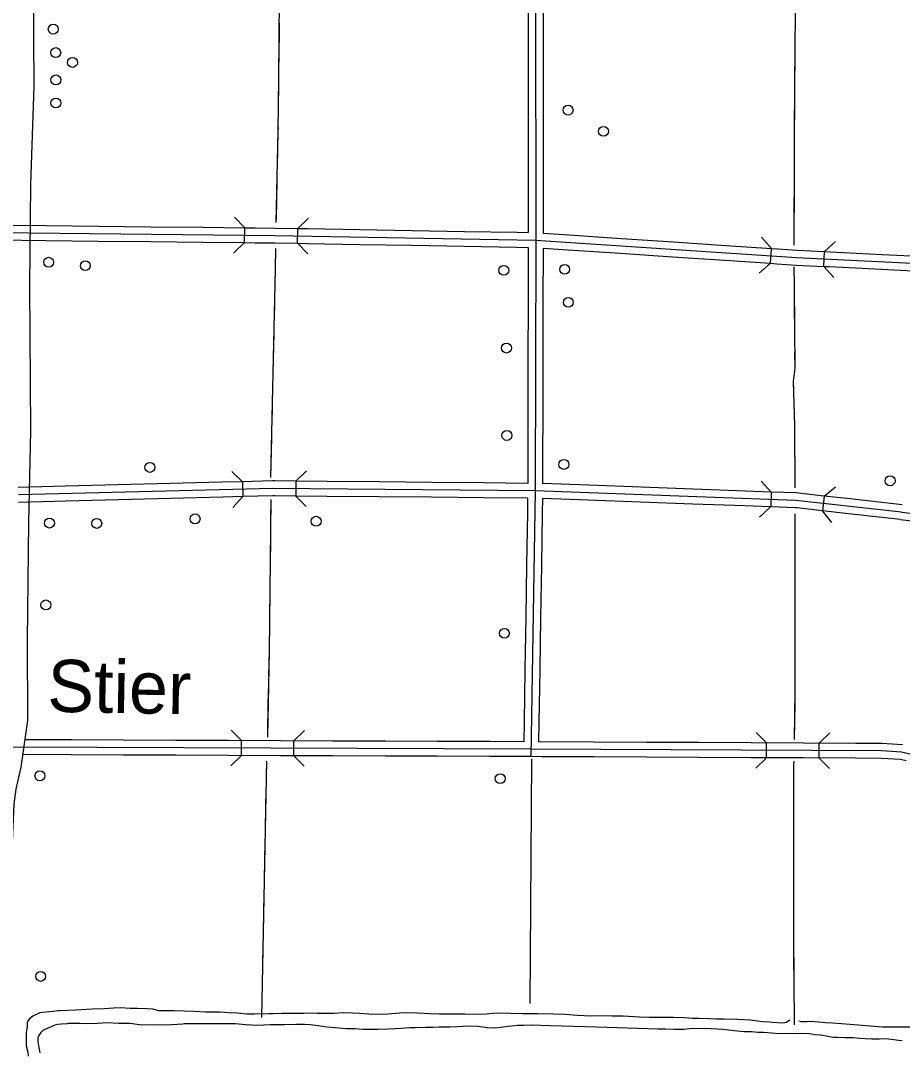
# Model space of a CAD drawing. Extents: x -4306 to 3843, y 131 to 8341.
# Drawn here: x -255 to 1170, y 190 to 1864 of the extents above; entities that cross this region are included whole.
import ezdxf

# ---------------------------------------------------------------- set-up
doc = ezdxf.new("R2010")
doc.units = 0
for name, color, linetype in [('10', 7, 'Continuous'), ('24', 7, 'Continuous'), ('32', 7, 'Continuous'), ('38', 7, 'Continuous'), ('52', 7, 'Continuous'), ('56', 7, 'Continuous'), ('57', 7, 'Continuous')]:
    doc.layers.add(name, color=color, linetype=linetype)

msp = doc.modelspace()

# ---------------------------------------------------------------- linework, layer by layer
at = {"layer": '10'}
msp.add_lwpolyline([(-229.9, 2753.2), (-230.3, 2716.3), (-231, 2305.2), (-234.2, 1917.5), (-233.4, 1758), (-238.7, 1599), (-240.3, 1434.8), (-238.9, 1200.9), (-242.2, 1053.5), (-244.1, 861.8), (-243.5, 732.4), (-254.4, 657.4), (-262.5, 621.4), (-265.5, 597.6), (-272.4, 440.2), (-274.5, 304.9), (-274.4, 293.9)], dxfattribs=at)
at = {"layer": '32'}
for p, q in [((577.4, 1912.9), (577.5, 1509.2)), ((565.4, 1901.4), (565.4, 1828.4)), ((589.4, 1900.3), (589.4, 1828.4)), ((565.4, 1828.4), (565.4, 1743.9)), ((589.4, 1828.4), (589.4, 1743.9)), ((565.4, 1743.9), (565.5, 1659.4)), ((589.4, 1743.9), (589.5, 1659.5)), ((565.5, 1659.4), (565.5, 1575)), ((589.5, 1659.5), (589.5, 1575)), ((565.5, 1575), (565.5, 1521.4)), ((589.5, 1575), (589.5, 1520.4)), ((-1096.1, 1530.1), (156, 1516.7)), ((-298, 1533.5), (-213.6, 1532.6)), ((-213.6, 1532.6), (-129.1, 1531.7)), ((-129.1, 1531.7), (-44.6, 1530.8)), ((-44.6, 1530.8), (39.9, 1529.9)), ((39.9, 1529.9), (107.4, 1529.2)), ((107.2, 1505.2), (107.4, 1529.2)), ((107.4, 1529.2), (124.4, 1529)), ((124.4, 1529), (156.1, 1528.7)), ((156.1, 1528.7), (192.9, 1528)), ((192.5, 1504), (193, 1528)), ((192.9, 1528), (208.9, 1527.7)), ((208.9, 1527.7), (293.4, 1526.3)), ((293.4, 1526.3), (377.9, 1524.8)), ((377.9, 1524.8), (462.4, 1523.3)), ((-298.3, 1509.5), (-213.8, 1508.6)), ((-213.8, 1508.6), (-129.3, 1507.7)), ((-129.3, 1507.7), (-44.8, 1506.8)), ((-44.8, 1506.8), (39.6, 1505.9)), ((156, 1516.7), (577.5, 1509.2)), ((462.4, 1523.3), (546.8, 1521.8)), ((546.8, 1521.8), (565.5, 1521.4)), ((577.5, 1509.2), (576.7, 1103.9)), ((577.5, 1509.2), (999.1, 1480.9)), ((589.5, 1520.4), (631.8, 1517.6)), ((631.8, 1517.6), (716.1, 1511.9)), ((716.1, 1511.9), (800.4, 1506.3)), ((39.6, 1505.9), (107.2, 1505.2)), ((107.2, 1505.2), (124.1, 1505)), ((124.1, 1505), (155.8, 1504.7)), ((155.8, 1504.7), (192.5, 1504)), ((192.5, 1504), (208.5, 1503.7)), ((208.5, 1503.7), (293, 1502.3)), ((293, 1502.3), (377.5, 1500.8)), ((377.5, 1500.8), (461.9, 1499.3)), ((461.9, 1499.3), (546.4, 1497.8)), ((546.4, 1497.8), (565.5, 1497.4)), ((565.5, 1497.4), (565.3, 1406)), ((589.5, 1496.4), (589.3, 1406)), ((589.5, 1496.4), (630.2, 1493.7)), ((630.2, 1493.7), (714.5, 1488)), ((800.4, 1506.3), (884.7, 1500.6)), ((884.7, 1500.6), (958.4, 1495.7)), ((956.8, 1471.7), (958.4, 1495.7)), ((958.4, 1495.7), (969, 1495)), ((969, 1495), (999.8, 1492.9)), ((999.8, 1492.9), (1044.4, 1490.7)), ((1042.9, 1466.7), (1044.1, 1490.7)), ((1044.4, 1490.7), (1053.1, 1490.3)), ((1053.1, 1490.3), (1137.5, 1486.1)), ((714.5, 1488), (798.8, 1482.3)), ((798.8, 1482.3), (883.1, 1476.7)), ((883.1, 1476.7), (956.6, 1471.7)), ((999.1, 1480.9), (1414, 1460.6)), ((1137.5, 1486.1), (1221.9, 1482)), ((956.8, 1471.7), (967.4, 1471)), ((967.4, 1471), (998.4, 1468.9)), ((998.4, 1468.9), (1043.2, 1466.7)), ((1043.2, 1466.7), (1052, 1466.3)), ((1052, 1466.3), (1136.4, 1462.2)), ((1136.4, 1462.2), (1220.7, 1458)), ((565.3, 1406), (565.1, 1321.5)), ((589.3, 1406), (589.1, 1321.5)), ((565.1, 1321.5), (565, 1237)), ((589.1, 1321.5), (589, 1237)), ((565, 1237), (564.8, 1152.5)), ((589, 1237), (588.8, 1152.5)), ((564.8, 1152.5), (564.7, 1116)), ((588.8, 1152.5), (588.7, 1115.5)), ((-182.2, 1111.3), (-258.4, 1109.3)), ((152.6, 1107.8), (-258.3, 1097.3)), ((-97.7, 1113.4), (-182.2, 1111.3)), ((-13.3, 1115.6), (-97.7, 1113.4)), ((71.2, 1117.8), (-13.3, 1115.6)), ((104, 1118.6), (71.2, 1117.8)), ((152.5, 1119.8), (104, 1118.6)), ((104, 1118.6), (104.6, 1094.6)), ((156.1, 1119.8), (152.5, 1119.8)), ((576.7, 1103.9), (152.6, 1107.8)), ((190.2, 1119.5), (156.1, 1119.8)), ((190.2, 1119.5), (189.9, 1095.5)), ((240.6, 1119), (190.2, 1119.5)), ((325, 1118.2), (240.6, 1119)), ((409.5, 1117.5), (325, 1118.2)), ((494, 1116.7), (409.5, 1117.5)), ((564.7, 1116), (494, 1116.7)), ((663.3, 1112.8), (588.7, 1115.5)), ((747.7, 1109.7), (663.3, 1112.8)), ((832.1, 1106.5), (747.7, 1109.7)), ((916.6, 1103.4), (832.1, 1106.5)), ((-97.1, 1089.5), (-181.6, 1087.3)), ((-12.7, 1091.6), (-97.1, 1089.5)), ((71.8, 1093.8), (-12.7, 1091.6)), ((104.6, 1094.6), (71.8, 1093.8)), ((152.7, 1095.8), (104.6, 1094.6)), ((155.9, 1095.8), (152.7, 1095.8)), ((189.9, 1095.5), (155.9, 1095.8)), ((240.3, 1095), (189.9, 1095.5)), ((324.8, 1094.2), (240.3, 1095)), ((409.3, 1093.5), (324.8, 1094.2)), ((493.8, 1092.7), (409.3, 1093.5)), ((564.5, 1092), (493.8, 1092.7)), ((564.5, 1092), (564.1, 1068.2)), ((576.7, 1103.9), (569.9, 674.2)), ((997.9, 1088.4), (576.7, 1103.9)), ((588.5, 1091.5), (588.1, 1067.8)), ((662.4, 1088.8), (588.5, 1091.5)), ((746.8, 1085.7), (662.4, 1088.8)), ((957.9, 1101.9), (916.6, 1103.4)), ((958, 1101.9), (957.2, 1077.9)), ((998.8, 1100.4), (957.9, 1101.9)), ((1168.5, 1069.5), (997.9, 1088.4)), ((1001.9, 1100.1), (998.8, 1100.4)), ((1043.5, 1095.5), (1001.9, 1100.1)), ((1043.5, 1095.5), (1040.8, 1071.6)), ((1085.8, 1090.7), (1043.5, 1095.5)), ((1169.8, 1081.4), (1085.8, 1090.7)), ((-181.6, 1087.3), (-258.2, 1085.3)), ((831.2, 1082.6), (746.8, 1085.7)), ((915.7, 1079.5), (831.2, 1082.6)), ((957.2, 1077.9), (915.7, 1079.5)), ((997.1, 1076.5), (957.2, 1077.9)), ((999.2, 1076.2), (997.1, 1076.5)), ((1040.8, 1071.6), (999.2, 1076.2)), ((1083.2, 1066.9), (1040.8, 1071.6)), ((564.1, 1068.2), (562.8, 983.7)), ((588.1, 1067.8), (586.8, 983.4)), ((1167.1, 1057.5), (1083.2, 1066.9)), ((1167.1, 1057.6), (1251, 1047.7)), ((1168.5, 1069.5), (1332.2, 1050.3)), ((562.8, 983.7), (561.4, 899.3)), ((586.8, 983.4), (585.4, 898.9)), ((561.4, 899.3), (560.1, 814.8)), ((585.4, 898.9), (584.1, 814.4)), ((560.1, 814.8), (558.8, 730.3)), ((584.1, 814.4), (582.8, 729.9)), ((558.8, 730.3), (558.3, 698.2)), ((582.8, 729.9), (582.3, 698.1)), ((-172.7, 701.2), (-248, 701.5)), ((-88.2, 700.8), (-172.7, 701.2)), ((-3.7, 700.5), (-88.2, 700.8)), ((80.8, 700.2), (-3.7, 700.5)), ((165.3, 699.8), (80.8, 700.2)), ((102.2, 676.1), (102.3, 700.1)), ((249.8, 699.5), (165.3, 699.8)), ((186.8, 675.7), (186.9, 699.7)), ((334.2, 699.1), (249.8, 699.5)), ((418.7, 698.8), (334.2, 699.1)), ((503.2, 698.5), (418.7, 698.8)), ((558.3, 698.2), (503.2, 698.5)), ((672.2, 697.7), (582.3, 698.1)), ((756.7, 697.3), (672.2, 697.7)), ((841.2, 696.9), (756.7, 697.3)), ((925.7, 696.5), (841.2, 696.9)), ((1010.2, 696.1), (925.7, 696.5)), ((950.4, 672.3), (950.5, 696.4)), ((1094.6, 695.7), (1010.2, 696.1)), ((1035.6, 671.9), (1035.7, 695.9)), ((1136.7, 695.4), (1094.6, 695.7)), ((1170.2, 693.5), (1136.7, 695.4)), ((-172.8, 677.2), (-251.5, 677.5)), ((-88.3, 676.8), (-172.8, 677.2)), ((-3.8, 676.5), (-88.3, 676.8)), ((80.7, 676.2), (-3.8, 676.5)), ((165.2, 675.8), (80.7, 676.2)), ((249.7, 675.5), (165.2, 675.8)), ((334.1, 675.1), (249.7, 675.5)), ((418.6, 674.8), (334.1, 675.1)), ((503.1, 674.5), (418.6, 674.8)), ((569.9, 674.2), (503.1, 674.5)), ((587.6, 674.1), (569.9, 674.2)), ((672.1, 673.7), (587.6, 674.1)), ((756.6, 673.3), (672.1, 673.7)), ((841.1, 672.9), (756.6, 673.3)), ((925.6, 672.5), (841.1, 672.9)), ((1010, 672.1), (925.6, 672.5)), ((1094.5, 671.6), (1010, 672.1)), ((1136, 671.4), (1094.5, 671.6)), ((1166.7, 669.6), (1136, 671.4)), ((1175.9, 667.4), (1166.7, 669.6))]:
    msp.add_line(p, q, dxfattribs=at)
msp.add_lwpolyline([(2052.2, 1131.5), (2052.1, 731.6), (2051.2, 728.2), (2048.7, 726.1), (1900.1, 653.4), (1410.3, 639.5), (1370.3, 641.2), (1252.7, 662.8), (1223, 668.4), (1168.4, 681.6), (1136.3, 683.4), (569.9, 686.2), (-271.6, 689.6)], dxfattribs=at)
at = {"layer": '38'}
for p, q in [((107.3, 1517.2), (107.3, 1517.2)), ((192.7, 1516), (192.7, 1516)), ((957.6, 1483.7), (957.6, 1483.7)), ((1043.8, 1478.7), (1043.8, 1478.7))]:
    msp.add_line(p, q, dxfattribs=at)
for points in [[(107.4, 1529.2), (90.7, 1546.4)], [(210.2, 1544.7), (193, 1528)], [(958.4, 1495.7), (942.6, 1513.7)], [(1062.2, 1506.8), (1044.4, 1490.7)], [(90, 1488.4), (107.2, 1505.2)], [(192.5, 1504), (209.2, 1486.8)], [(938.7, 1455.9), (956.8, 1471.7)], [(1043.2, 1466.7), (1059.4, 1448.9)], [(86.6, 1135.1), (104, 1118.6)], [(190.2, 1119.5), (207.3, 1136.3)], [(941.6, 1119.5), (957.9, 1101.9)], [(1043.5, 1095.5), (1062.2, 1110.4)], [(104.6, 1094.6), (88.1, 1077.2)], [(206.8, 1078.4), (189.9, 1095.5)], [(957, 1077.9), (939.4, 1061.6)], [(1055.8, 1052.9), (1040.8, 1071.6)], [(85.4, 717.1), (102.3, 700.1)], [(186.9, 699.7), (203.9, 716.6)], [(933.7, 713.4), (950.5, 696.4)], [(1035.7, 695.9), (1052.8, 712.8)], [(102.2, 676.1), (85.2, 659.2)], [(203.7, 658.7), (186.8, 675.7)], [(950.4, 672.3), (933.4, 655.5)], [(1052.5, 654.9), (1035.6, 671.9)]]:
    msp.add_lwpolyline(points, dxfattribs=at)
at = {"layer": '52'}
msp.add_line((570.9, 670.2), (568.3, 275.2), dxfattribs=at)
at = {"layer": '56'}
for points in [[(999.3, 2313.2), (999.2, 2286.4), (997.2, 2101.7), (996.6, 2003.3), (996.9, 1879.7), (995.5, 1749.8), (995.1, 1656.3), (994.6, 1501.8), (994.6, 1500.8)], [(163.4, 1912.9), (163.3, 1899.3), (162.2, 1772.3), (161.1, 1685.1), (157.9, 1537.8)], [(162.9, 1860.1), (162.4, 1796.7)], [(996.5, 1838), (996.1, 1806.3)], [(996.1, 1806.3), (995.8, 1774.6)], [(162.2, 1775.6), (162.2, 1772.3), (161.5, 1712.2)], [(995.5, 1753.5), (995.5, 1749.8), (995.3, 1690.1)], [(161.2, 1691.1), (161.1, 1685.1), (159.9, 1627.7)], [(995.2, 1669), (995.1, 1656.3), (995, 1605.6)], [(159.4, 1606.6), (158, 1543.3)], [(994.9, 1584.5), (994.7, 1521.1)], [(157.2, 1495.8), (156.8, 1462.7), (149, 1125.3)], [(157.2, 1495.8), (156.8, 1464.1)], [(994.7, 1466), (994.9, 1435.7), (996.1, 1302.2), (993.6, 1280.5), (995.8, 1209.4), (996.2, 1108.8)], [(994.7, 1466), (994.9, 1435.7), (994.9, 1434.3)], [(156.3, 1443), (154.8, 1379.6)], [(995.1, 1413.2), (995.6, 1349.8)], [(154.4, 1358.5), (152.9, 1295.2)], [(995.8, 1328.7), (996.1, 1302.2), (993.6, 1280.5), (994.1, 1265.5)], [(152.4, 1274), (151, 1210.7)], [(994.7, 1244.4), (995.8, 1209.4), (995.9, 1181)], [(150.5, 1189.6), (149, 1126.2)], [(996, 1159.9), (996.2, 1108.8)], [(149.7, 1089.9), (146.7, 844.5), (144, 705.7)], [(149.7, 1089.9), (149.3, 1058.2)], [(996.3, 1066.8), (996.1, 928.4), (996.5, 780.1), (995, 701.7)], [(996.3, 1066.8), (996.2, 1035.1)], [(149.1, 1037.1), (148.3, 973.7)], [(996.2, 1014), (996.1, 950.6)], [(148, 952.6), (147.2, 889.2)], [(996.1, 929.5), (996.1, 928.4), (996.3, 866.1)], [(147, 868.1), (146.7, 844.5), (145.9, 804.8)], [(996.3, 845), (996.5, 781.6)], [(145.5, 783.6), (144.2, 720.3)], [(996.2, 760.5), (995, 701.7)], [(135, 252.6), (143.2, 666.8)], [(142.7, 643.3), (143.2, 666.8)], [(994.4, 666.9), (994.3, 661.5), (994.1, 386.3), (995.2, 240.6)], [(994.4, 666.9), (994.3, 661.5), (994.3, 635.2)], [(141.1, 558.8), (142.3, 622.2)], [(994.2, 614.1), (994.2, 550.7)], [(139.4, 474.4), (140.6, 537.7)], [(994.2, 529.6), (994.2, 466.2)], [(137.7, 389.9), (139, 453.2)], [(994.2, 445.1), (994.1, 386.3), (994.2, 381.8)], [(136.1, 305.4), (137.3, 368.8)], [(994.3, 360.6), (994.8, 297.3)], [(123, 257.9), (110.7, 258), (95.2, 259.6), (81.9, 260.3), (67.7, 261.1), (44.6, 261.4), (25, 262.3), (9.3, 262.7), (-6.5, 263.2), (-31.6, 263.4), (-41.1, 265.8), (-50.2, 266.8), (-65.9, 267.2), (-77.9, 267.3), (-93.5, 268.1), (-104.4, 267.8), (-119.9, 266.8), (-139.3, 265.8), (-166, 264.2), (-191.3, 263.2)], [(994.9, 276.1), (995.1, 248.3)], [(-191.3, 263.2), (-194.5, 263.1), (-201.8, 262.4), (-208.2, 261.8), (-223.4, 260.1), (-234.1, 255.5), (-235.2, 254.7), (-239.1, 251.6), (-242.7, 247.7), (-244, 243.7), (-244.3, 236.9), (-245.8, 228.4), (-245.5, 219.8), (-245.7, 206.7), (-243, 196.7), (-242.3, 189.9)], [(224.3, 259.2), (212.7, 259.4), (202.6, 258.9), (187.7, 258.8), (166.5, 258.8), (152.6, 258.4), (146.6, 258.6), (123, 257.9)], [(988, 248.3), (982.9, 244.7), (976.2, 243.2), (959.7, 244.6), (955.9, 244.8), (944.2, 245.4), (935.7, 246.5), (923.4, 248.4), (903.4, 249.3), (882.3, 250.1), (869.8, 249.9), (858, 250.2), (840.6, 250.8), (830.8, 250.9), (818, 251.8), (800, 252.3), (780.6, 252.4), (760.9, 252.5), (745, 253.1), (718.7, 254.8), (701.1, 254.6), (684.8, 255.1), (667.6, 254.9), (644.4, 255.9), (625.7, 257.3), (607, 257.8), (581.4, 258.3), (556.4, 258.3), (536.4, 259.2), (514.4, 259.3), (497.6, 258.1), (481.3, 257.6), (462.9, 257.9), (445.2, 258), (422, 258.1), (406.3, 258.6), (386.6, 259.6), (371.1, 260.1), (358, 259.6), (338.5, 258.1), (323.5, 257.2), (307.7, 258), (293.3, 259.2), (281.4, 259.5), (266.4, 260.1), (252, 259.2), (237.5, 259), (224.3, 259.2)], [(-188.4, 241.6), (-194.4, 241.1), (-199.2, 240.3), (-216.4, 232.8), (-218.7, 231.3), (-221.9, 228.2), (-225.5, 223.6), (-227, 220.2), (-227.1, 213.5), (-225, 204.2), (-223.8, 195.7)], [(285.7, 234.5), (271.9, 234.3), (259.9, 235.3), (240.2, 236.8), (226.2, 239.2), (213.2, 240.9), (204.1, 241.4), (190.2, 241), (171.5, 240.8), (164, 240.8), (157.1, 240.6), (148.5, 240.6), (128, 239.6), (108.6, 240.8), (92.3, 242.3), (68.5, 242.2), (47.6, 242.1), (30.3, 242.1), (9.8, 242.1), (7.3, 241.9), (-2, 241.5), (-18.9, 240.4), (-34, 240.5), (-59.2, 240.4), (-77.8, 242.6), (-96.2, 242.9), (-114.9, 243.7), (-130.7, 243), (-146.1, 242.5), (-159.2, 243.1), (-178.5, 242.6), (-179.6, 242.5), (-188.4, 241.6)], [(1169.9, 214.7), (1163.5, 215.3), (1156.1, 216.4), (1143, 218.3), (1133.3, 217.8), (1128.2, 217.5), (1120.5, 217.3), (1109.9, 217.9), (1101.1, 218.7), (1090.7, 219.5), (1077.3, 219.9), (1065, 220), (1058, 220.5), (1049.5, 222.1), (1038, 224), (1029.3, 224.8), (1020, 225.9), (1005.2, 226.9), (993.7, 226.4), (981.5, 226.7), (971.1, 226.4), (958.5, 227.2), (945.5, 228.2), (937.1, 228.4), (926, 229.2), (914.3, 229.3), (908.4, 229.9), (893.9, 231.8), (879.6, 233.2), (870.5, 233.7), (860.9, 234), (841.9, 234.7), (825.3, 234.1), (817.6, 233.1), (810.6, 233.2), (801.9, 233.2), (786.6, 233.6), (775.2, 233.9), (675.8, 236.7), (600.8, 239), (570.1, 240), (557.4, 239.8), (547.9, 239.6), (543.9, 239.2), (532.7, 238), (521.3, 236.2), (512.1, 235.4), (499.6, 236), (484.2, 238.1), (468.2, 238.5), (450.7, 237.7), (439.6, 237.1), (430, 237.1), (421.1, 236.9), (411.3, 236.4), (400.3, 236.4), (383.3, 236), (374.1, 236), (360.3, 234.9), (339.7, 233.5), (322.8, 233), (311.7, 233.3), (298.5, 233.4), (285.7, 234.5)], [(1221.1, 245.6), (1212, 242.8), (1202.6, 241.1), (1194.3, 238.9), (1185.2, 237.2), (1177.8, 237), (1159, 236.9), (1138, 237), (1124.7, 238), (1104.9, 239.4), (1084.9, 241.1), (1071.8, 242.2), (1057.2, 243.6), (1045.7, 244), (1035, 244.8), (1022.2, 245.9), (1015.7, 245.7), (1006.9, 245.6), (1002.7, 246.8), (1002.7, 246.9)]]:
    msp.add_lwpolyline(points, dxfattribs=at)
at = {"layer": '57'}
for centre in [(-202, 1850.2), (-197.9, 1812.3), (-170.9, 1796.4), (-197.7, 1768.1), (-197.7, 1730.8), (629.9, 1719.3), (687, 1685), (-209.4, 1473.4), (-150.2, 1467.8), (526, 1460.3), (624.4, 1461.9), (630.3, 1408.6), (530.3, 1334.7), (531, 1193.4), (-45.9, 1141.8), (623, 1146.6), (1150.2, 1120.1), (-208.1, 1051.8), (-131.7, 1051.2), (27.2, 1058.6), (222.8, 1054.7), (-213.9, 919.5), (527, 873.6), (-223.5, 643.3), (520.2, 638.7), (-222.3, 319)]:
    msp.add_circle(centre, 8, dxfattribs=at)

# ---------------------------------------------------------------- texts
at = {"layer": '24'}
msp.add_text('Stier', height=84.49, rotation=358.9554, dxfattribs=at).set_placement((-212, 746.9))

doc.saveas('drawing.dxf')
